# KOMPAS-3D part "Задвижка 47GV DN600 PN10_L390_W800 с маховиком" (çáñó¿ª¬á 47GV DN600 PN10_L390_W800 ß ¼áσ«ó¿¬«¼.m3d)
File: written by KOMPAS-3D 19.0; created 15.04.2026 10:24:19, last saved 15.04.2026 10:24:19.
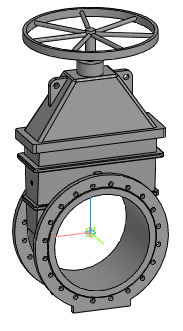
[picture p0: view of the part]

Document properties: Автор: Евгений; Полное имя файла: Z:\3.Личные\kachalov\3d для проектировщиков\2.1 Тип 47GV, 47GV.Z\Задвижка 47GV_DN40-DN600\stp_Задвижка 47GV\Задвижка 47GV DN600 PN10_L390_W800 с маховиком.m3d

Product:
- Part/product: Задвижка 47GV DN600 PN10_L390_W800 с маховиком

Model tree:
1. Операция без истории:1  (labels: Задвижка 47GV DN600 PN10_L390_W800 с маховиком)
